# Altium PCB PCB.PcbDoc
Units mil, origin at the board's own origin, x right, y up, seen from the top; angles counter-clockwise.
Board outline 1456.87 x 1673.29 mil, 2 copper layers (Top Layer, Bottom Layer); 37 components, 35 nets, 169 pads, 140 vias.
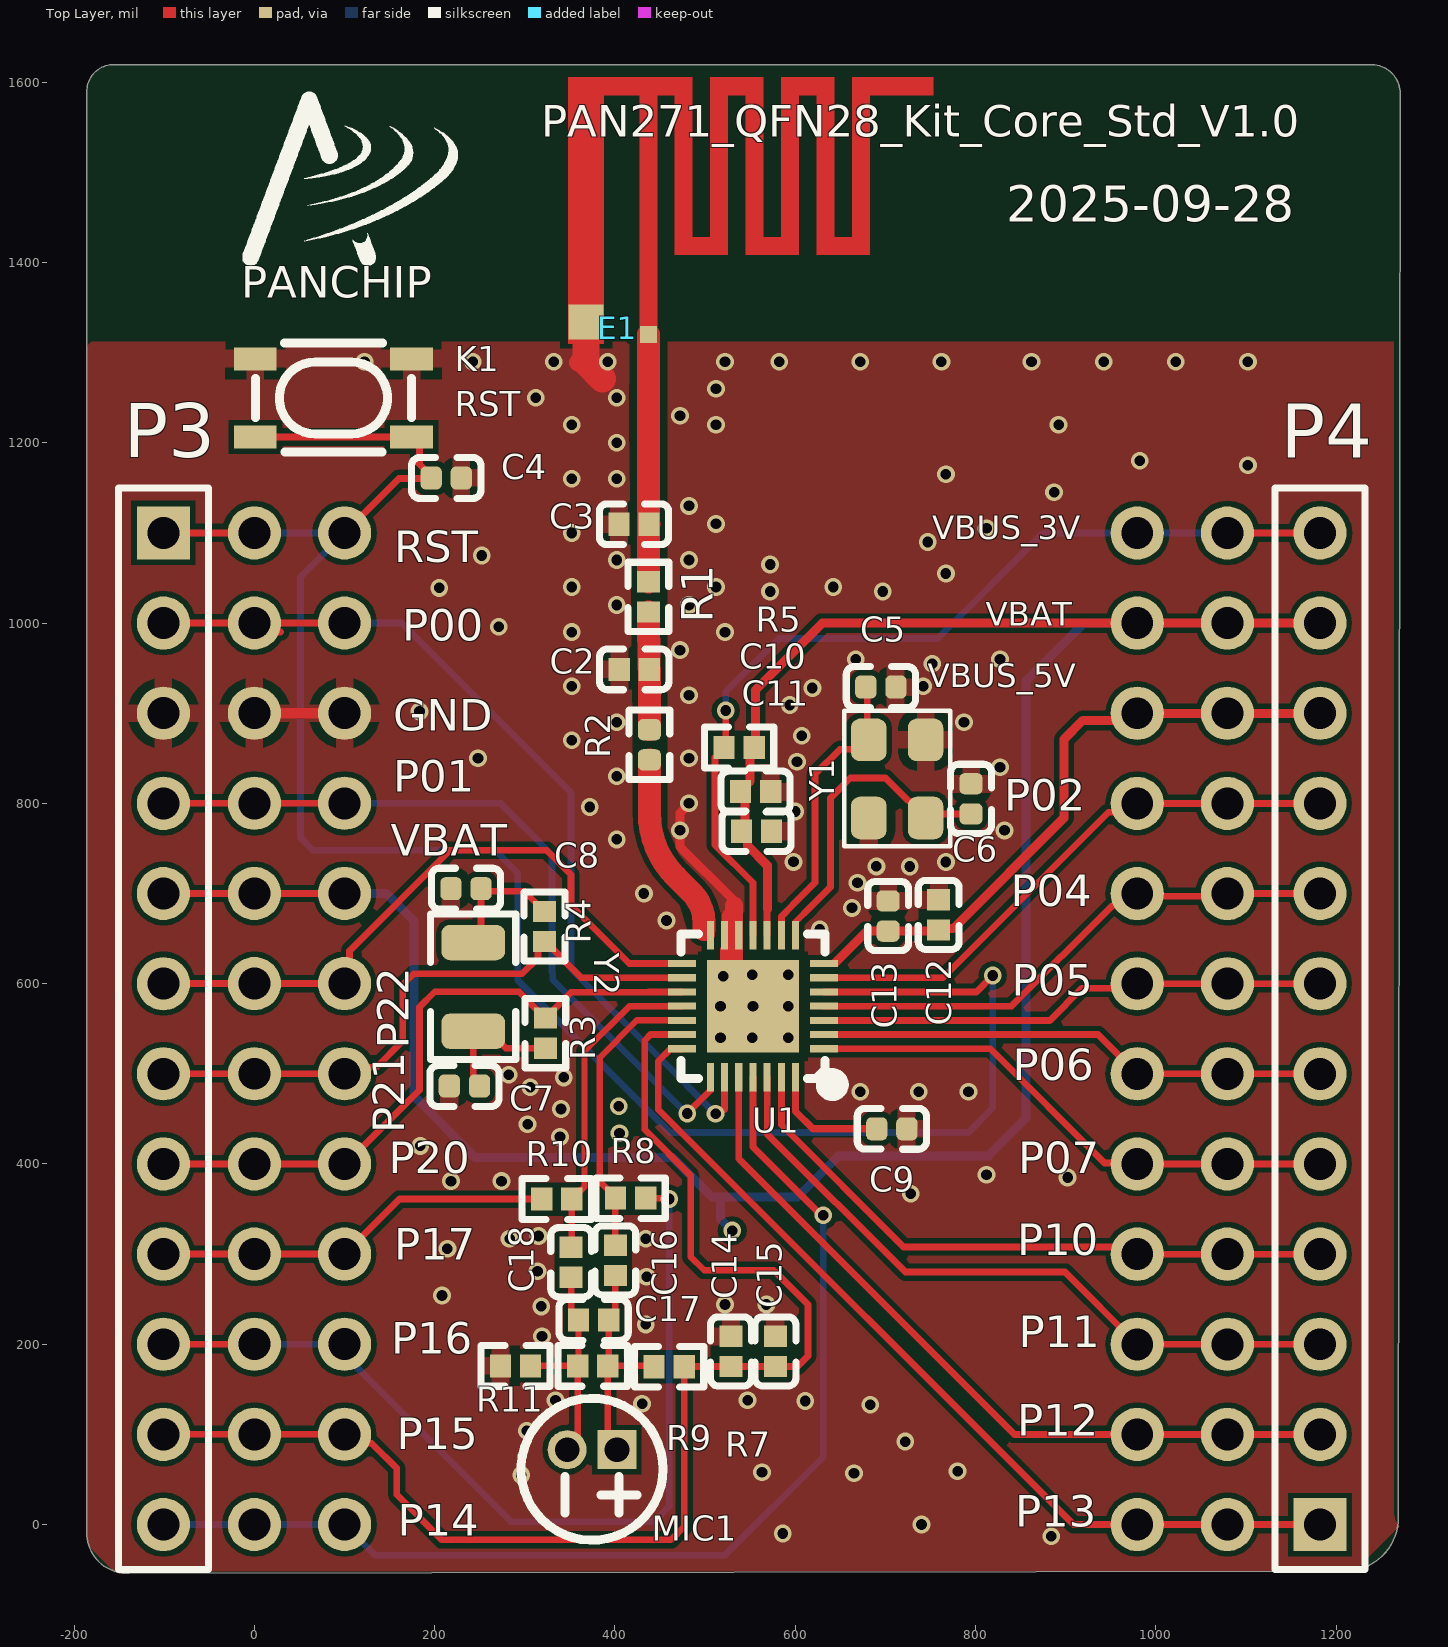
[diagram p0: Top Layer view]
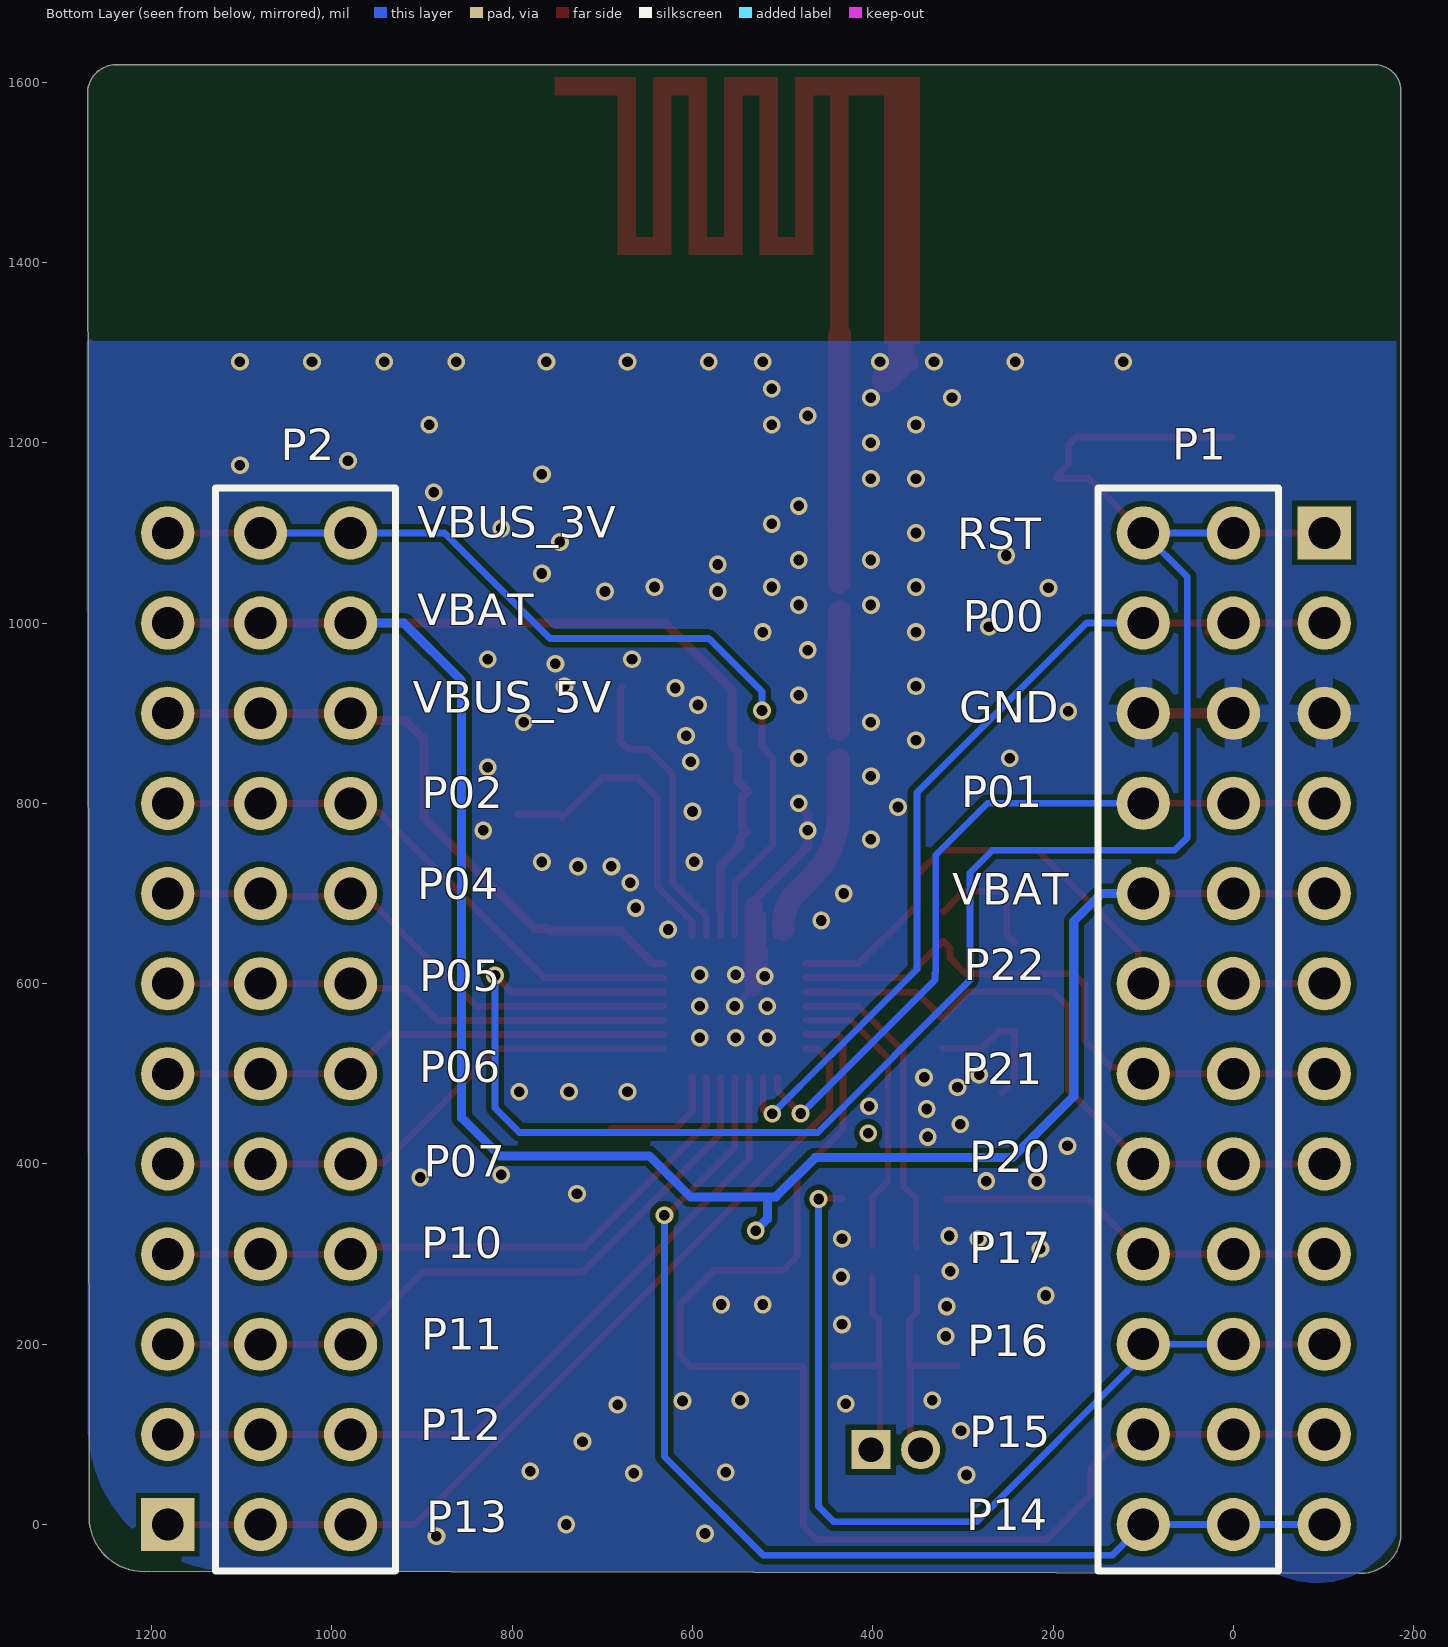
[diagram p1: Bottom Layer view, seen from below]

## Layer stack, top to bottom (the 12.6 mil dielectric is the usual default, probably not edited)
Top Solder: solder mask 0.4, Solder Resist, Dk 3.5
Top Layer: signal copper 1.4
Dielectric1: dielectric 12.6, FR-4, Dk 4.8
Bottom Layer: signal copper 1.4
Bottom Solder: solder mask 0.4, Solder Resist, Dk 3.5

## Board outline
-185.79,-12.05 -185.79,1588.95 cw(c-156.7,1590.15) -157.9,1619.24 1240.1,1619.24 cw(c1239.45,1587.61) 1271.08,1586.95 1269.1,2.95 cw(c1208.6,8.45) 1203.1,-52.05 1203.1,-52.07 -138.9,-54.05 cw(c-141.34,-9.6)

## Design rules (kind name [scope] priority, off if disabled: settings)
Clearance Clearance_SMT [OnLayer('Keep-Out Layer')] p1: gap=5 ignorepadtopadclearanceinfootprint=FALSE
Clearance Clearance_ANT [InNetClass('ANT_Class')] p2: gap=4.6 ignorepadtopadclearanceinfootprint=FALSE
Clearance [All] p3: gap=6 ignorepadtopadclearanceinfootprint=FALSE
ComponentClearance [All] p1 off: gap=10 collisioncheckmode=3 verticalgap=10 showdistances=FALSE
DiffPairsRouting [All] p1: maxlimit=10 minlimit=7 mostfreqgap=10 toplayer_minwidth=7 toplayer_maxwidth=15 toplayer_prefwidth=7 bottomlayer_minwidth=7 bottomlayer_maxwidth=15 bottomlayer_prefwidth=7 maxuncoupledlength=500
HoleSize [All] p1: absolutevalues=TRUE maxlimit=100 minlimit=10 maxpercent=80.000 minpercent=20.000
HoleToHoleClearance [All] p1: gap=7.87 allowstackedmicrovias=TRUE
MinimumSolderMaskSliver MinimumSolderMaskSliver_1 [HasFootprint('QFN-28_5x5x05P')] p1: minsoldermaskwidth=0.66
MinimumSolderMaskSliver [All] p2: minsoldermaskwidth=0.8
NetAntennae [All] p1 off: netantennaetolerance=0
PlaneConnect [All] p1: planeconnectstyle=Relief reliefexpansion=20 reliefentries=4 reliefconductorwidth=20 reliefairgap=10
PolygonConnect PolygonConnect_VIA [IsVia] p1: connectstyle=Direct reliefconductorwidth=10 reliefentries=4 polygonreliefangle="90 Angle" airgapwidth=10
PolygonConnect [All] p2: connectstyle=Relief reliefconductorwidth=20 reliefentries=4 polygonreliefangle="90 Angle" airgapwidth=10
RoomDefinition ANT [False] p1: confinementstyle=ConfineIn formatcopy=TRUE lockcomponents=FALSE outline 278,1614.13 994,1614.13 994,1263.74 278,1263.74
RoutingVias [All] p1: holewidth=15.75 width=19.68 viastyle="Through Hole" minholewidth=11.81 minwidth=19.68 maxholewidth=19.68 maxwidth=27.56
ShortCircuit ShortCircuit_ANT [WithinRoom('ANT')] p1: allowed=TRUE
ShortCircuit [All] p2: allowed=FALSE
SilkToSilkClearance [All] p1: silktosilkclearance=0
SilkToSolderMaskClearance SilkToSolderMaskClearance_U10 [HasFootprint('U2')] p1: minsilkscreentomaskgap=2 clearancetoexposedcopper=TRUE
SilkToSolderMaskClearance [IsPad] p2: minsilkscreentomaskgap=0 clearancetoexposedcopper=TRUE
SolderMaskExpansion SolderMaskExpansion_1 [IsVia] p1: expansion=4 istentingtop=FALSE
SolderMaskExpansion [ALL] p2: expansion=4 istentingtop=FALSE soldermaskfromhole=TRUE
Width [All] p1: maxlimit=50 minlimit=7.5 preferedwidth=7.5
20 further rules are at their usual default settings.

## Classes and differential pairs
differential pair mic1: +mic1_p -mic1_n
differential pair mic: +mic_p -mic_n

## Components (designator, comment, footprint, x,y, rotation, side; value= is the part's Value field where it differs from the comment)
C2 "NC" 0402_C#1 421.37,948.6 r180 top
C3 "NC" 0402_C#1 421.1,1109.57 r180 top
C4 "100nF / NC" 0402_C#2 212.84,1160.95 r180 top
C5 "NC" 0402_C#2 695,929 r0 top
C6 "NC" 0402_C#2 795,805 r90 top
C7 "18pF" 0402_C#2 233,486.37 r180 top
C8 "18pF" 0402_C#2 234.74,705.37 r180 top
C9 "NC" 0402_C#2 707.1,438.95 r180 top
C10 "4.7uF" 0402_C#1 556,813 r180 top
C11 "100nF" 0402_C#1 557,769 r180 top
C12 "100nF" 0402_C#1 759.1,676.22 r270 top
C13 "4.7uF" 0402_C#2 703.1,674.95 r270 top
C14 "4.7uF" 0402_C#1 528.64,191.95 r270 top
C15 "100nF" 0402_C#1 578,192 r270 top
C16 "1uF" 0402_C#1 400.37,292.95 r270 top
C17 "NC" 0402_C#1 376.37,226.95 r180 top
C18 "1uF" 0402_C#1 351.37,290.95 r270 top
E1 "ANT_PCB" 2.4G_PF_SUB1.5mm_ADD1 368,1322 r90 top
K1 "K2-1808GN-A4SW-04" KEY-SMD_4P-L4.2-W3.2-P2.20-LS5.1-TL 87.71,1249.65 r180 top
MIC1 "GMI4015P-2C-60db" MIC-TH_BD4.0-P1.40-D0.4-L-FD 374.54,82.95 r180 top
P1 "Header 2x12" "Header 2X12" 100,1100 r270 bottom locked
P2 "Header 2x12" "Header 2X12" 1079.34,1099.9 r270 bottom locked
P3 "nc" HDR1X12 -100.9,1099.95 r270 top
P4 "nc" HDR1X12 1182.1,-0.05 r90 top
R1 "0Ω" 0402_R#1 437,1029 r90 top
R2 "0Ω" 0402_R#2 438.1,864.95 r90 top
R3 "NC" 0402_R#1 322.74,545.1 r270 top
R4 "NC" 0402_R#1 321.74,663.37 r90 top
R5 "NC" 0402_R#1 537.73,862 r180 top
R7 "2.2KΩ" 0402_R#1 460.1,174.95 r0 top
R8 "nc" 0402_R#1 417.37,361.95 r180 top
R9 "NC" 0402_R#1 375.37,175.95 r0 top
R10 "nc" 0402_R#1 335.37,360.95 r0 top
R11 "2.2KΩ" 0402_R#1 289.64,175.95 r0 top
U1 "pn271_qfn28" QFN28_L4.0_W4.0_P0.40_BL_EP 553.1,574.95 r90 top
Y1 "32MHz 10pF ±10ppm" SMD-3225_4P_S 713,827 r90 top
Y2 "32.768KHz" "SMD-3215_2P FC - 135" 242.74,596.37 r90 top

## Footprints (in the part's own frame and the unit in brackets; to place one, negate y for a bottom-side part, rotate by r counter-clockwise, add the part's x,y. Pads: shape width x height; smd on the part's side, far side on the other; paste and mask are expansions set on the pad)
2.4G_PF_SUB1.5mm_ADD1 [mil] "FR4_PCB with 1.6mm thickness"
  rect 19x19 smd: 1(-2,-69)
  rect 39x39 smd: 2(12,0)
  Top Layer region: 283.31,-19.48 283.31,19.89 -12,19.89 -12,-19.48
  Top Layer region: 283.31,-314.76 263.61,-314.76 263.61,-385 283.31,-385
  Top Layer region: 283.31,-236.02 283.31,-216.33 86.46,-216.33 86.46,-236.02 283.31,-236.02
  Top Layer region: 283.31,-314.76 283.31,-295.07 86.46,-295.07 86.46,-314.76 283.31,-314.76
  Top Layer region: 283.31,-196.64 283.31,-176.96 86.46,-176.96 86.46,-196.64 283.31,-196.64
  Top Layer region: 283.31,-275.39 283.31,-255.7 86.46,-255.7 86.46,-275.39 283.31,-275.39
  Top Layer region: 283.31,-157.28 283.31,-137.59 86.46,-137.59 86.46,-157.28 283.31,-157.28
  Top Layer region: 283.31,-255.7 283.31,-236.02 263.62,-236.02 263.62,-255.7 283.31,-255.7
  Top Layer region: 283.31,-117.91 283.31,-19.48 263.62,-19.48 263.62,-98.22 86.46,-98.22 86.46,-117.91 283.31,-117.91
  Top Layer region: 283.31,-176.96 283.31,-157.28 263.62,-157.28 263.62,-176.96 283.31,-176.96
  Top Layer region: 106.14,-137.59 106.14,-117.91 86.46,-117.91 86.46,-137.59 106.14,-137.59
  Top Layer region: 106.14,-275.39 86.46,-275.39 86.46,-295.07 106.14,-295.07 106.14,-275.39
  Top Layer region: 106.14,-216.33 106.14,-196.65 86.46,-196.65 86.46,-216.33 106.14,-216.33
  Top Layer region: 263.79,-79.16 263.79,-59.48 -12,-59.48 -12,-79.16
0402_C#1 [mm]
  rect 0.6x0.65 smd mask+0.051: 1(-0.425,0) 2(0.425,0)
  silkscreen extent -0.97,-0.58 0.97,0.58, body extent -0.48,-0.3 0.52,0.3, height 0.2
0402_C#2 [mm]
  rrect50% 0.6x0.65 smd mask+0.051: 1(-0.425,0) 2(0.425,0)
  silkscreen extent -0.97,-0.58 0.98,0.58, body extent -0.48,-0.3 0.52,0.3, height 0.2
0402_R#1 [mm]
  rect 0.6x0.65 smd mask+0.051: 1(-0.425,0) 2(0.425,0)
  silkscreen extent -0.97,-0.58 0.97,0.58, body extent -0.57,-0.27 0.58,0.28, height 0.41
0402_R#2 [mm]
  rrect50% 0.6x0.65 smd mask+0.051: 1(-0.425,0) 2(0.425,0)
  silkscreen extent -0.97,-0.58 0.97,0.58, body extent -0.57,-0.27 0.58,0.28, height 0.41
HDR1X12 [mm] "Connector; Header; 12 Position"
  rect 1.5x1.5 hole 0.9: 1(0,0)
  round 1.5 hole 0.9: 2(2.54,0) 3(5.08,0) 4(7.62,0) 5(10.16,0) 6(12.7,0) 7(15.24,0) 8(17.78,0) 9(20.32,0) 10(22.86,0) 11(25.4,0) 12(27.94,0)
  silkscreen extent -1.27,-1.27 29.21,1.27
"Header 2X12" [mm] "Connector; Header; 12x2 Position"
  round 1.5 hole 0.9: 1(0,0) 2(0,2.54) 3(2.54,0) 4(2.54,2.54) 5(5.08,0) 6(5.08,2.54) 7(7.62,0) 8(7.62,2.54) 9(10.16,0) 10(10.16,2.54) 11(12.7,0) 12(12.7,2.54) 13(15.24,0) 14(15.24,2.54) 15(17.78,0) 16(17.78,2.54) 17(20.32,0) 18(20.32,2.54) 19(22.86,0) 20(22.86,2.54) 21(25.4,0) 22(25.4,2.54) 23(27.94,0) 24(27.94,2.54)
  silkscreen extent -1.27,-1.27 29.25,3.81, body extent -1.27,-1.27 29.21,3.81, height 8.5
KEY-SMD_4P-L4.2-W3.2-P2.20-LS5.1-TL [mm]
  rect 1.2x0.65 smd: 1(-2.2,1.1) 2(2.2,1.1) 3(-2.2,-1.1) 4(2.2,-1.1)
  silkscreen extent -2.2,-1.55 2.2,1.52
MIC-TH_BD4.0-P1.40-D0.4-L-FD [mm]
  rect 1.1x1.1 hole 0.7: 1(-0.7,0)
  round 1.1 hole 0.7: 2(0.7,0)
  silkscreen extent -2,-1.45 2,2.55
QFN28_L4.0_W4.0_P0.40_BL_EP [mm] "271_qfn28_sram"
  rect 0.2x0.8 smd: 1(-1.2,-2) 2(-0.8,-2) 3(-0.4,-2) 4(0,-2) 5(0.4,-2) 6(0.8,-2) 7(1.2,-2) 15(1.2,2) 16(0.8,2) 17(0.4,2) 18(0,2) 19(-0.4,2) 20(-0.8,2) 21(-1.2,2)
  rect 0.8x0.2 smd: 8(2,-1.2) 9(2,-0.8) 10(2,-0.4) 11(2,0) 12(2,0.4) 13(2,0.8) 14(2,1.2) 22(-2,1.2) 23(-2,0.8) 24(-2,0.4) 25(-2,0) 26(-2,-0.4) 27(-2,-0.8) 28(-2,-1.2)
  rect 2.6x2.6 smd: 29(0,0)
  silkscreen extent -2.03,-2.03 2.03,2.03
"SMD-3215_2P FC - 135" [mm]
  rrect50% 1x1.8 smd: 1(-1.25,0) 2(1.25,0)
  silkscreen extent -2.05,-1.2 2.05,1.2, body extent -1.6,-0.75 1.6,0.75, height 0.9
SMD-3225_4P_S [mm]
  rrect50% 1.2x1 smd: 1(1.1,0.8) 2(-1.1,0.8) 3(-1.1,-0.8) 4(1.1,-0.8)
  silkscreen extent -1.9,-1.5 1.92,1.5, body extent -1.6,-1.25 1.6,1.25, height 0.7

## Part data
C2 C3: library part "0402 1nF (102) 10% 50V", "贴片电容", Package=0402, SuppliersPartNumber=C1523
C4 C9 C13: library part "0402 100nF (104) 10% 16V", "贴片电容", Package=0402, SuppliersPartNumber=C1525
C5 C6 C7 C8: library part "0402 20pF (200) 5% 50V", "贴片电容", Package=0402, SuppliersPartNumber=C1554
C10 C11 C12 C14 C15 C16 C17 C18: library part "0402 4.7uF (475) 20% 10V", "贴片电容", Package=0402, SuppliersPartNumber=C23733
E1: "2.4GHz PCB ANTENNA"
K1: Contact Current=50mA, Insulation Resistance=100MΩ, JLCPCB Part Class="Extended Part", Manufacturer=韩国韩荣, Operating Force=250gf, Operating Temperature=-25℃~+85℃, Voltage Rating (DC)=12V
MIC1: JLCPCB Part Class="Extended Part", LCSC Part Name="全指向双电容φ4.0*1.5mm 1.5V-10V 灵敏度-60dB 低阻抗", Manufacturer=INGHAi(赢海)
P1 P2: "Header 2x11,2.54mm"
P3 P4: library part "Header 12", "Header, 12-Pin"
R1 R2 R3 R4 R5 R8 R9 R10 R11: library part "0402 0Ω (0R0) 1%", "贴片电阻", Package=0402, SuppliersPartNumber=C17168
R7: library part "0402 2.2KΩ (2201) 1%", "贴片电阻", Package=0402, SuppliersPartNumber=C25879
Y1: library part "Crystal 4pin", "C113671"
Y2: library part "DT26N 32.768KHz", "C620155, X321532768KGD2SI,12.5pF"

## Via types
v1: diameter 19.68, hole 11.81, Top Layer to Bottom Layer, tented both sides, 133 vias
v2: diameter 19.68, hole 11.81, Top Layer to Bottom Layer, 7 vias

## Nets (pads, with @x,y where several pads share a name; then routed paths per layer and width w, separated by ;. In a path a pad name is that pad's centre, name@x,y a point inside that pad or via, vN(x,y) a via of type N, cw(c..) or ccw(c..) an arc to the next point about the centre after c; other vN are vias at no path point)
ANT: R2.1 U1.14 | length 233.9
  Top Layer w10: 500.56,679.19 cw(c487.77,666.39) 505.86,666.39 U1.14
  Top Layer w25.59: R2.1 438.1,789.37 ccw(c538.1,789.37) 467.39,718.66 485.1,700.95 cw(c451.87,667.71) 498.87,667.71 498.87,660.04
GND: C2.2 C3.2 C4.1 C5.2 C6.2 C7.2 C8.2 C9.1 C10.1 C11.1 C12.1 C13.1 C14.1 C15.1 E1.2 K1.3 K1.4 P1.5 P1.6 P3.3 R11.1 U1.12 U1.13 U1.29 Y1.2 Y1.4 | length 582.6
  Top Layer w7.5: 532.1,686.65 522.12,676.68 522.12,670.26 521.79,669.92 521.79,653.88 U1.13 521.42,653.5 521.42,639.12 520,637.71 520,633 v1(520.01,608.04) 532.1,595.95 v1(553.1,574.95)
  Top Layer w10: v1(482.1,799.95) 482.1,799.25 472.1,789.25 v1(472.1,769.95) 472.1,751.9 532.1,691.9 532.1,686.65
  Top Layer w11.81: P1.6 P1.5
  Top Layer w20: 359,1289 366.22,1296.22 366.22,1332.22 E1.2 ; U1.29@532.1,595.95 532.1,686.65
  Top Layer w30: E1.2 368,1289 386,1271
  other v1: 884.1,-13.05 586.1,-10.05 740.1,-0.05 296.1,54.95 665.1,56.95 563.1,57.95 780.1,58.95 722.1,91.95 302.1,103.95 683.1,132.95 430.1,133.95 611.1,136.95 334.1,137.95 547.1,137.95 319.1,208.95 434.1,221.95 318.1,241.95 522,244 568,244 208.1,253.95 435.1,274.95 314.1,280.95 214.1,305.95 283.1,316.95 434.1,316.95 315.1,319.95 728.1,366.95 218.1,380.95 274.1,380.95 902.1,384.95 812.1,387.95 184.1,419.95 339.1,429.95 303.1,443.95 340.1,460.95 404.1,463.95 672.1,479.95 737.1,479.95 792.1,479.95 306.1,484.95 343.1,495.95 282.1,498.95 517.1,539.95 552.1,539.95 592.1,539.95 517.1,574.95 592.1,574.95 552.1,609.95 592.1,609.95 627.1,659.95 457.1,669.95 663,684 432.1,699.95 669,712 690,730 727.1,729.95 598,735 767.1,734.95 402.1,759.95 832.1,769.95 600,791 372.1,795.95 402.1,829.95 827.1,839.95 602,846 248.1,849.95 482.1,849.95 352.1,869.95 607.1,874.95 402.1,889.95 787.1,889.95 183.1,901.95 594,909 482.1,919.95 619,928 352.1,929.95 742.1,929.95 752.1,954.95 667.1,959.95 827.1,959.95 472.1,969.95 352.1,989.95 522.1,989.95 271.1,995.95 402.1,1019.95 482.1,1019.95 572.1,1034.95 697.1,1034.95 205.1,1038.95 352.1,1039.95 512.1,1039.95 642.1,1039.95 767.1,1054.95 572.1,1064.95 402.1,1069.95 482.1,1069.95 252.1,1074.95 747.1,1089.95 352.1,1099.95 812.1,1104.95 512.1,1109.95 482.1,1129.95 887.1,1144.95 352.1,1159.95 402.1,1159.95 767.1,1164.95 1102.1,1174.95 982.1,1179.95 402.1,1199.95 352.1,1219.95 512.1,1219.95 892.1,1219.95 472.1,1229.95 312.1,1249.95 402.1,1249.95 512.1,1259.95 122.1,1289.95 242.1,1289.95 332.1,1289.95 392.1,1289.95 522.1,1289.95 582.1,1289.95 672.1,1289.95 762.1,1289.95 862.1,1289.95 942.1,1289.95 1022.1,1289.95 1102.1,1289.95
mic1_n: C18.1 R10.2 U1.18 | length 353.3
  Top Layer w7: C18.1 352.1,308.42 R10.2 352.1,361.94 360.41,370.25 362,370.25 366.1,374.35 366.1,524.99 416.06,574.95 U1.18
mic1_p: C16.1 R8.2 U1.19 | length 324
  Top Layer w7: C16.1 400.37,361.68 R8.2 400.64,362.94 383.1,380.47 383.1,517.95 424.36,559.21 U1.19
mic_n: C17.2 C18.2 MIC1.2 R9.1 R11.2 | length 252.2
  Top Layer w7: R11.2 R9.1 ; MIC1.2 346.98,84.22 358.64,95.87 R9.1 ; C18.2 351.37,235.22 C17.2 359.64,176.95 R9.1
mic_p: C16.2 C17.1 MIC1.1 R7.1 R9.2 | length 252.5
  Top Layer w7: C16.2 400.37,234.22 C17.1 393.1,176.95 R9.2 ; MIC1.1 399.97,85.08 399.97,87.64 392.1,95.51 R9.2 ; R7.1 442.37,175.95 R9.2
NetC2_1: C2.1 R1.1 R2.2 | length 131
  Top Layer w23.62: C2.1@437.77,949.91 438.1,949.58 C2.1
  Top Layer w25.59: R1.1 437,981.48 437.77,980.7 C2.1@437.77,949.91 ; R2.2 438.1,896.88 C2.1
NetC3_1: C3.1 E1.1 R1.2 | length 275
  Top Layer w25.59: R1.2 437,1108.74 C3.1 437,1110.41 E1.1
NetC7_1: C7.1 R3.2 Y2.1 | length 161.4
  Top Layer w7.5: C7.1@256.76,479.35 C7.1 249.74,488.52 242.74,495.52 Y2.1 260.03,547.16 278.81,528.37 R3.2
NetC8_1: C8.1 R4.2 Y2.2 | length 143.5
  Top Layer w7.5: Y2.2 251.47,654.32 C8.1@251.47,702.37 ; C8.1 C8.1@251.47,702.37 ; R4.2 320.75,680.1 312.69,688.17 312.69,689.15 299.47,702.37 C8.1@251.47,702.37
NetC9_2: C9.2 U1.28 | length 136
  Top Layer w7.87: U1.28 600.34,458.2 619.59,438.95 C9.2
P00: P1.3 P1.4 P3.2 U1.23 | length 1023.8
  Top Layer w7.5: P3.2 P1.4 P1.4 ; 28.99,990.14 9.86,990.14 4.93,995.07 9.86,1000 P1.3 ; v2(511.6,455.54) 514.9,455.54 519.82,460.46 521.52,460.46 521.6,460.54 U1.23
  Bottom Layer w7.5: P1.3 163.05,1000 351.1,811.95 351.1,615.95 447.1,519.95 447.2,519.95 v2(511.6,455.54)
P01: P1.7 P1.8 P3.4 U1.22 | length 856.8
  Top Layer w7.5: P3.4 -100.85,800 P1.8 P1.7 ; v2@479.01,454.85 505.67,481.51 505.67,496.02 U1.22
  Bottom Layer w7.5: P1.7 273.05,800 330.1,742.95 330.1,612.86 331.1,611.86 331.1,603.95 479.1,455.95 v2(480.1,455.95)
P02: P2.7 P2.8 P4.9 U1.6 | length 630.4
  Top Layer w7.5: U1.6 763.6,606.45 947.19,790.04 969.48,790.04 P2.8 P2.7 1182.05,799.9 P4.9
P03: C4.2 K1.1 K1.2 P1.1 P1.2 P3.1 U1.5 | length 2234.4
  Top Layer w7.5: P3.1 -100.85,1100 P1.2 ; K1.2 K1.1 183.1,1197.56 183.1,1176.1 196.1,1163.1 C4.2 195.4,1160.25 160.25,1160.25 P1.1 ; U1.5 800.85,590.7 v2(819.1,608.95)
  Bottom Layer w7.5: P1.2 P1.1 51.1,1051.1 51.1,761.95 65.1,747.95 267.1,747.95 292.1,722.95 292.1,603.95 461.1,434.95 792.1,434.95 819.1,461.95 v2(819.1,608.95)
P04: P2.9 P2.10 P4.8 U1.4 | length 604.5
  Top Layer w7.5: U1.4 840.1,574.95 950.86,685.71 951.2,685.71 965.39,699.9 P2.10 982.29,696.95 1076.39,696.95 P2.9 1079.39,699.95 P4.8
P05: P2.11 P2.12 P4.7 U1.3 | length 567.1
  Top Layer w7.5: U1.3 882.36,559.21 918.1,594.95 974.39,594.95 P2.12 P2.11 1182.05,599.9 P4.7
P06: P2.13 P2.14 P4.6 U1.2 | length 568.3
  Top Layer w7.5: U1.2 935.78,543.46 P2.14 P2.13 1182.05,499.9 P4.6
P07: P2.15 P2.16 P4.5 U1.1 | length 572
  Top Layer w7.5: U1.1 816.34,527.71 942.96,401.1 978.15,401.1 P2.16 979.39,399.95 1048.1,399.95 ; P2.15 1182.05,399.9 P4.5
P10: P2.17 P2.18 P4.4 U1.27 | length 709.7
  Top Layer w7.5: U1.27 584.6,443.45 720.1,307.95 971.29,307.95 P2.18 P2.17 1182.05,299.9 P4.4
P11: P2.19 P2.20 P4.3 U1.26 | length 772.9
  Top Layer w7.5: U1.26 568.85,433.2 722.1,279.95 899.29,279.95 P2.20 P2.19 1182.05,199.9 P4.3
P12: P1.23 P1.24 P3.12 U1.25 | length 1246.1
  Top Layer w7.5: U1.25 553.1,418.9 628,344 630.35,344 v2(631.17,343.17)
  Bottom Layer w7.5: P3.12 P1.24 P1.24 P1.23 134,-34 522,-34 631.17,75.17 v2(631.17,343.17)
P13: P2.21 P2.22 P4.2 U1.24 | length 862
  Top Layer w7.5: U1.24 537.35,405.65 843.1,99.9 P2.22 P2.21 1182.05,99.9 P4.2
P14: P2.23 P2.24 P4.1 U1.21 | length 1010.5
  Top Layer w7.5: U1.21 474.18,527.52 461.52,527.52 448,514 448,460.35 908.44,-0.1 P2.24 P2.23 1182.05,-0.1 P4.1
P15: C14.2 C15.2 P1.21 P1.22 P3.11 R7.2 U1.20 | length 1482.7
  Top Layer w7.5: P3.11 -100.85,100 P1.22 P1.21 109.86,90.14 129.86,90.14 158,62 158,33 208,-17 462,-17 476.84,-2.16 R7.2 477.1,175.22 C14.2 577.95,175.22 C15.2 602.27,175.27 614,187 614,244 579,279 576,282 499,282 484,297 484,387 433,438 433,537 439.46,543.46 U1.20
P16_DIP: P1.19 P1.20 P3.10 R8.1 | length 1024.2
  Top Layer w7.5: P3.10 -100.85,200 P1.20 ; R8.1 459.22,361.95 v2(460.14,361.03)
  Bottom Layer w7.5: P1.20 P1.19 100,188.05 285.1,2.95 443.14,2.95 460.14,19.95 v2(460.14,361.03)
P17_DIP: P1.17 P1.18 P3.9 R10.1 | length 444.8
  Top Layer w7.5: P3.9 -100.85,300 P1.18 P1.17 160.95,360.95 R10.1
P20: P1.15 P1.16 P3.8 R3.1 U1.17 | length 739.9
  Top Layer w7.5: P3.8 -100.85,400 P1.16 P1.15 112.1,400 112.1,410.95 183.1,481.95 183.1,573.95 200.1,590.95 293.62,590.95 313.69,570.88 313.69,569.9 321.75,561.84 R3.1 323.72,561.84 331.78,569.9 331.78,570.88 351.23,590.33 436.73,590.33 437.1,590.7 U1.17
P21: P1.13 P1.14 P3.7 R4.1 U1.16 | length 695.5
  Top Layer w7.5: P3.7 -100.85,500 P1.14 P1.13 107.26,507.26 135.41,507.26 164.53,536.38 164.53,598.38 177.1,610.95 297.1,610.95 314.51,628.35 314.51,639.41 R4.1 322.72,646.64 362.91,606.45 U1.16
P22: P1.11 P1.12 P3.6 U1.15 | length 726.6
  Top Layer w7.5: P3.6 -100.85,600 P1.12 P1.11 105.54,605.54 105.54,636.38 217.1,747.95 324.1,747.95 351.1,720.95 351.1,686.95 415.85,622.2 U1.15
VBAT: C10.2 C11.2 P1.9 P1.10 P2.3 P2.4 P3.5 P4.11 R5.1 U1.10 | length 2881
  Top Layer w7.5: P3.5 -100.85,700 P1.10 P1.9 ; 568.66,682.55 568.66,668.26 568.67,653.88 U1.10
  Top Layer w10: v2(530,326) v2@533,326 ; R5.1 R5.1@556.1,863.64 ; 569.2,682.55 569.2,730.81 547.08,752.92 547.08,762.19 C11.2 544.4,773.13 544.4,807.87 C10.2 539.27,813.98 549.92,824.64 549.92,857.46 R5.1@556.1,863.64 ; P4.11 1182.05,999.9 P2.3 P2.4 630.05,999.9 556.1,925.95 R5.1@556.1,863.64
  Bottom Layer w10: P1.9 146.05,700 177.1,668.95 177.1,474.95 245.1,406.95 464.05,406.95 507.5,363.5 517,363.5 ; v2(530,326) 517,339 517,363.5 ; P2.4 920.05,999.9 856.1,935.95 856.1,451 814.1,409 648,409 602.5,363.5 517,363.5
VBUS_3V: P2.1 P2.2 P4.12 R5.2 U1.11 | length 1024.7
  Top Layer w7.5: v2(523,903) 523,863.02 511,851.02 511,754 553.1,711.9 U1.11 ; P2.1 1182.05,1099.9 P4.12
  Bottom Layer w7.5: v2(523,903) 523,924 581.95,982.95 758.1,982.95 875.05,1099.9 P2.2 P2.1
VBUS_5V: C12.2 C13.2 P2.5 P2.6 P4.10 U1.7 | length 715.8
  Top Layer w7.5: U1.7 U1.7@644.41,622.2 ; C12.2@757.84,658.22 C12.2
  Top Layer w10: U1.7@644.41,623.26 679.37,658.22 C13.2 C12.2@757.84,658.22 ; C12.2 760.57,660.95 775.1,660.95 898.1,783.95 898.1,870.95 919.1,891.95 971.39,891.95 P2.6 P2.5 1182.05,899.9 P4.10
XC0: C5.1 U1.9 Y1.1 | length 329.4
  Top Layer w7.5: U1.9 584.64,653.73 584.64,674.49 597.12,686.96 597.12,687.12 622,712 622,832.33 649.59,859.92 670.12,859.92 671.14,859.94 Y1.1 679.89,871.93 679.89,927.38 C5.1
XC1: C6.1 U1.8 Y1.3 | length 354
  Top Layer w7.5: U1.8 600.53,653.88 600.53,668.64 617.95,686.05 618.05,686.05 639,707 639,806 661,828 700.19,828 725.27,802.92 725.91,802.92 744.5,784.33 Y1.3@744.5,783.87 ; Y1.3 Y1.3@744.5,783.87 ; C6.1 748.89,788.27 Y1.3@744.5,783.87
copper on no net:
  other v1: 405.1,433.95

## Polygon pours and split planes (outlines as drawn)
GND on Bottom Layer "GND_L02_P001" (solid, remove dead copper, pour order 1): -180.9,-12.05 -180.9,1385.14 cw(c-43.4,1385.14) -43.39,1522.64 1106.12,1522.64 cw(c1106.64,1357.33) 1271.96,1356.8 1271.08,112.71 cw(c1106.64,112.28) 1106.21,-52.16 -43.39,-52.16 cw(c-92.09,36.64)
GND on Top Layer "GND_L01_P003" (solid, pour order 3): -184.9,1403.95 ccw(c-182.48,1401.54) -185.9,1401.54 -185.9,-12.05 ccw(c-161.75,-12.05) -178.83,-29.12 -154.9,-53.05 cw(c-152.48,-55.46) -152.48,-52.05 1221.1,-52.05 cw(c1223.52,-52.05) 1221.81,-50.34 1270.1,-2.05 cw(c1284.59,12.44) 1264.1,12.44 1264.1,1406.95

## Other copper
Top Layer:
  pour cut-out: 415.68,1312.09 458.57,1312.09 458.57,773.55 470.68,744.32 512.95,693.02 521.6,653.69 511.1,644.95 491.54,642.34 479.71,660.04 471.55,687.4 431.93,735.27 420.1,797.95 415.1,1222.97
  pour cut-out: -185.79,1619.24 -185.79,1312.09 1269.1,1312.09 1269.1,1619.24
Bottom Layer:
  pour cut-out: -185.79,1312.7 336,1312.7 1264.7,1312.7 1269.1,1317.1 1269.1,1619.24 -185.79,1619.24

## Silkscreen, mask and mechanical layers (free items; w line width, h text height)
Top Overlay:
  drawing of 1098 lines, arcs and shapes, not listed
  text "PAN271_QFN28_Kit_Core_Std_V1.0" at 318,1528 h60
  text "2025-09-28" at 834,1445 h40
  text "PANCHIP" at -14.79,1349.46 h60
  text "RST" at 222.1,1219.95 h47.24
  text "VBUS_3V" at 752.1,1083.95 h45
  text "RST" at 155.1,1055.95 h60
  text "VBAT" at 811.1,987.95 h45
  text "P00" at 164.1,968.95 h60
  text "VBUS_5V" at 747,920 h45
  text "GND" at 154.1,868.95 h60
  text "P01" at 154.1,800.95 h60
  text "P02" at 832.1,779.95 h60
  text "VBAT" at 151.1,729.95 h60
  text "P04" at 839.1,673.95 h60
  text "P05" at 840.1,574.95 h60
  text "P22" at 183.1,527.95 h60 r90
  text "P06" at 841.1,480.95 h60
  text "P21" at 178.1,433.95 h60 r90
  text "P20" at 149.1,377.95 h60
  text "P07" at 847.1,377.95 h60
  text "P10" at 846.1,286.95 h60
  text "P17" at 155.1,281.95 h60
  text "P11" at 848.1,184.95 h60
  text "P16" at 152.1,177.95 h60
  text "P12" at 846.1,86.95 h60
  text "P15" at 158.1,71.95 h60
  text "P13" at 844.1,-14.05 h60
  text "P14" at 159.1,-24.05 h60
Bottom Overlay:
  text "VBUS_3V" at 905.1,1082.95 h60
  text "RST" at 306.1,1069.95 h60
  text "VBAT" at 905.1,985.95 h60
  text "P00" at 300.1,978.95 h60
  text "VBUS_5V" at 910.1,888.95 h60
  text "GND" at 304.1,877.95 h60
  text "P01" at 302.1,783.95 h60
  text "P02" at 900.1,782.95 h60
  text "P04" at 905.1,681.95 h60
  text "VBAT" at 312.1,675.95 h60
  text "P22" at 299.1,591.95 h60
  text "P05" at 903.1,579.95 h60
  text "P06" at 903.1,478.95 h60
  text "P21" at 302.1,476.95 h60
  text "P20" at 293.1,378.95 h60
  text "P07" at 898.1,373.95 h60
  text "P10" at 901.1,283.95 h60
  text "P17" at 293.1,277.95 h60
  text "P11" at 901.1,181.95 h60
  text "P16" at 295.1,174.95 h60
  text "P12" at 902.1,81.95 h60
  text "P15" at 293.1,73.95 h60
  text "P14" at 296.1,-18.05 h60
  text "P13" at 895.1,-20.05 h60
Mechanical 1:
  lines w3.94: -185.79,-12.05 ccw(c-141.34,-9.6) -138.9,-54.05 1203.1,-52.07 ccw(c1208.6,8.45) 1269.1,2.95 1271.08,1586.95 ccw(c1239.45,1587.61) 1240.1,1619.24 -157.9,1619.24 ccw(c-156.7,1590.15) -185.79,1588.95 -185.79,-12.05

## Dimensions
-185.79,1588.95 to 1269.1,2.95 on Top Overlay
-157.9,1619.24 to -138.9,-54.05 on Top Overlay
